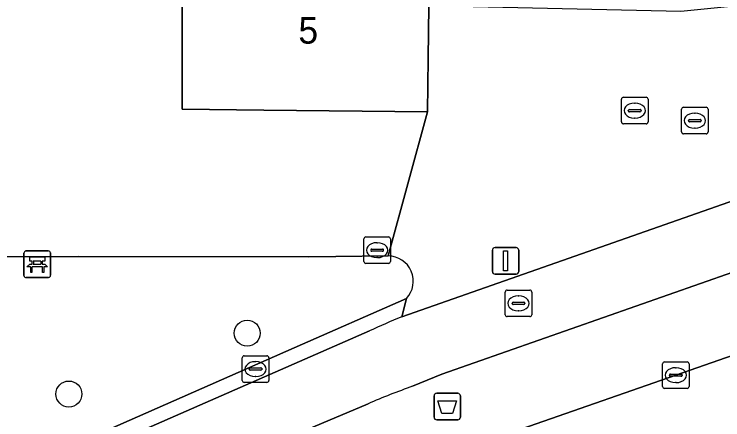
# Model space of a CAD drawing. Extents: x 161087 to 161926, y 382572 to 383873.
# Drawn here: x 161727.08 to 161753.78, y 382829.54 to 382844.81 of the extents above; entities that cross this region are included whole.
import ezdxf

# ---------------------------------------------------------------- set-up
doc = ezdxf.new("R2010")
doc.units = 0
for name, color, linetype in [('IMGEO_Afvalbak', 7, 'Continuous'), ('IMGEO_Bank', 7, 'Continuous'), ('IMGEO_Boom', 7, 'Continuous'), ('IMGEO_Fietspad_gesloten', 7, 'Continuous'), ('IMGEO_Groenvoorziening', 7, 'Continuous'), ('IMGEO_Kolk', 7, 'Continuous'), ('IMGEO_Lichtmast', 7, 'Continuous'), ('IMGEO_Pand', 7, 'Continuous'), ('IMGEO_Pand_nummerreeks', 7, 'Continuous'), ('IMGEO_Rijbaan_lokaal_gesloten', 7, 'Continuous'), ('IMGEO_Rioolput', 7, 'Continuous'), ('IMGEO_Voetpad_open', 7, 'Continuous')]:
    doc.layers.add(name, color=color, linetype=linetype)

msp = doc.modelspace()

# ---------------------------------------------------------------- linework, layer by layer
at = {"layer": 'IMGEO_Afvalbak'}
for p, q in [((161742.903, 382829.642), (161742.903, 382830.442)), ((161742.903, 382830.442), (161742.903, 382829.642)), ((161743.003, 382830.542), (161743.793, 382830.542)), ((161743.793, 382830.542), (161743.003, 382830.542)), ((161743.893, 382830.442), (161743.893, 382829.642)), ((161743.893, 382829.642), (161743.893, 382830.442)), ((161743.793, 382829.542), (161743.003, 382829.542)), ((161743.003, 382829.542), (161743.793, 382829.542))]:
    msp.add_line(p, q, dxfattribs=at)
msp.add_lwpolyline([(161743.046, 382830.256), (161743.75, 382830.256), (161743.601, 382829.786), (161743.195, 382829.786), (161743.046, 382830.256)], dxfattribs=at)
for centre, start, end in [((161743.003, 382830.442), 90, 180), ((161743.003, 382830.442), 90, 180), ((161743.793, 382830.442), 0, 90), ((161743.793, 382830.442), 360, 90), ((161743.003, 382829.642), 180, 270), ((161743.003, 382829.642), 180, 270), ((161743.793, 382829.642), 270, 0), ((161743.793, 382829.642), 270, 0)]:
    msp.add_arc(centre, 0.1, start, end, dxfattribs=at)
at = {"layer": 'IMGEO_Bank'}
for p, q in [((161727.449, 382834.974), (161727.449, 382835.815)), ((161727.449, 382835.815), (161727.449, 382834.974)), ((161727.524, 382835.899), (161728.365, 382835.899)), ((161728.365, 382835.899), (161727.524, 382835.899)), ((161728.449, 382835.824), (161728.449, 382834.983)), ((161728.449, 382834.983), (161728.449, 382835.824)), ((161727.758, 382835.405), (161727.758, 382835.511)), ((161727.802, 382835.511), (161727.802, 382835.405)), ((161728.09, 382835.517), (161727.808, 382835.517)), ((161728.096, 382835.405), (161728.096, 382835.511)), ((161728.14, 382835.511), (161728.14, 382835.405)), ((161728.146, 382835.297), (161727.753, 382835.297)), ((161727.808, 382835.399), (161728.09, 382835.399)), ((161728.374, 382834.899), (161727.533, 382834.899)), ((161727.533, 382834.899), (161728.374, 382834.899))]:
    msp.add_line(p, q, dxfattribs=at)
for points in [[(161727.752, 382835.517), (161727.666, 382835.517), (161727.666, 382835.678), (161728.229, 382835.678), (161728.229, 382835.517), (161728.146, 382835.517)], [(161727.696, 382835.297), (161727.554, 382835.297), (161727.666, 382835.399), (161727.752, 382835.399)], [(161727.746, 382835.29), (161727.746, 382835.083), (161727.703, 382835.083), (161727.703, 382835.29)], [(161728.146, 382835.399), (161728.229, 382835.399), (161728.341, 382835.297), (161728.202, 382835.297)], [(161728.196, 382835.29), (161728.196, 382835.083), (161728.152, 382835.083), (161728.152, 382835.29)]]:
    msp.add_lwpolyline(points, dxfattribs=at)
for centre, radius, start, end in [((161727.527, 382835.821), 0.0779, 92.4484, 184.2845), ((161727.527, 382835.821), 0.0779, 92.4484, 184.2845), ((161728.371, 382835.821), 0.0779, 2.4484, 94.2845), ((161728.371, 382835.821), 0.0779, 2.4484, 94.2845), ((161727.751, 382835.51), 0.00671, 2.8957, 87.1043), ((161727.808, 382835.51), 0.00671, 92.8957, 177.1043), ((161728.09, 382835.51), 0.00671, 2.8957, 87.1043), ((161728.147, 382835.51), 0.00671, 92.8957, 177.1043), ((161727.696, 382835.29), 0.00671, 2.8957, 87.1043), ((161727.753, 382835.29), 0.00671, 92.8957, 177.1043), ((161727.751, 382835.406), 0.00671, 272.8957, 357.1043), ((161727.808, 382835.406), 0.00671, 182.8957, 267.1043), ((161728.09, 382835.406), 0.00671, 272.8957, 357.1043), ((161728.147, 382835.406), 0.00671, 182.8957, 267.1043), ((161728.145, 382835.29), 0.00671, 2.8957, 87.1043), ((161728.202, 382835.29), 0.00671, 92.8957, 177.1043), ((161727.527, 382834.977), 0.0779, 182.4484, 274.2845), ((161727.527, 382834.977), 0.0779, 182.4484, 274.2845), ((161728.371, 382834.977), 0.0779, 272.4484, 4.2845), ((161728.371, 382834.977), 0.0779, 272.4484, 4.2845)]:
    msp.add_arc(centre, radius, start, end, dxfattribs=at)
at = {"layer": 'IMGEO_Boom'}
for centre in [(161735.859, 382832.805), (161729.142, 382830.513)]:
    msp.add_circle(centre, 0.489, dxfattribs=at)
at = {"layer": 'IMGEO_Fietspad_gesloten'}
for points in [[(161770.191, 382843.404), (161741.681, 382833.418)], [(161742.093, 382830.806), (161743.191, 382831.256), (161763.899, 382838.518), (161770.624, 382840.877)], [(161740.467, 382832.888), (161719.327, 382823.646), (161720.925, 382819.562), (161728.389, 382822.563), (161727.398, 382824.655), (161740.413, 382830.148)]]:
    msp.add_lwpolyline(points, dxfattribs=at)
for centre, radius, start, end in [((161752.523, 382806.929), 28.622, 112.2588, 114.9108), ((161751.235, 382804.991), 27.385, 109.5008, 113.2764)]:
    msp.add_arc(centre, radius, start, end, dxfattribs=at)
at = {"layer": 'IMGEO_Groenvoorziening'}
for points in [[(161741.172, 382835.713), (161739.196, 382835.695), (161738.184, 382835.679), (161729.521, 382835.693), (161717.159, 382835.65)], [(161719.905, 382824.464), (161737.635, 382832.249), (161741.859, 382834.108)]]:
    msp.add_lwpolyline(points, dxfattribs=at)
msp.add_arc((161741.164, 382834.76), 0.953, 316.8324, 89.513, dxfattribs=at)
at = {"layer": 'IMGEO_Kolk'}
for p, q in [((161749.961, 382840.757), (161749.961, 382841.609)), ((161750.036, 382841.683), (161750.888, 382841.683)), ((161750.962, 382841.609), (161750.962, 382840.757)), ((161750.449, 382841.463), (161750.474, 382841.463)), ((161750.22, 382841.177), (161750.22, 382841.189)), ((161750.658, 382841.14), (161750.26, 382841.14)), ((161750.263, 382841.226), (161750.661, 382841.226)), ((161750.704, 382841.189), (161750.704, 382841.177)), ((161750.472, 382840.903), (161750.447, 382840.903)), ((161750.888, 382840.683), (161750.036, 382840.683)), ((161740.254, 382835.503), (161740.254, 382836.355)), ((161740.329, 382836.429), (161741.181, 382836.429)), ((161741.255, 382836.355), (161741.255, 382835.503)), ((161740.742, 382836.209), (161740.767, 382836.209)), ((161740.513, 382835.923), (161740.513, 382835.935)), ((161740.951, 382835.886), (161740.553, 382835.886)), ((161740.556, 382835.972), (161740.954, 382835.972)), ((161740.997, 382835.935), (161740.997, 382835.923)), ((161740.765, 382835.649), (161740.74, 382835.649)), ((161741.181, 382835.429), (161740.329, 382835.429)), ((161745.656, 382834.427), (161746.508, 382834.427)), ((161745.581, 382833.501), (161745.581, 382834.353)), ((161746.069, 382834.207), (161746.094, 382834.207)), ((161746.582, 382834.353), (161746.582, 382833.501)), ((161745.84, 382833.921), (161745.84, 382833.933)), ((161746.278, 382833.884), (161745.88, 382833.884)), ((161745.883, 382833.97), (161746.281, 382833.97)), ((161746.324, 382833.933), (161746.324, 382833.921)), ((161746.092, 382833.647), (161746.067, 382833.647)), ((161746.508, 382833.427), (161745.656, 382833.427)), ((161735.675, 382831.026), (161735.675, 382831.878)), ((161735.75, 382831.952), (161736.602, 382831.952)), ((161736.163, 382831.732), (161736.188, 382831.732)), ((161736.676, 382831.878), (161736.676, 382831.026)), ((161751.584, 382831.723), (161752.436, 382831.723)), ((161735.934, 382831.446), (161735.934, 382831.458)), ((161735.977, 382831.495), (161736.375, 382831.495)), ((161736.418, 382831.458), (161736.418, 382831.446)), ((161751.509, 382830.797), (161751.509, 382831.649)), ((161751.997, 382831.503), (161752.022, 382831.503)), ((161752.51, 382831.649), (161752.51, 382830.797)), ((161736.372, 382831.409), (161735.974, 382831.409)), ((161751.768, 382831.217), (161751.768, 382831.229)), ((161751.811, 382831.266), (161752.209, 382831.266)), ((161752.252, 382831.229), (161752.252, 382831.217)), ((161736.602, 382830.952), (161735.75, 382830.952)), ((161736.186, 382831.172), (161736.161, 382831.172)), ((161752.206, 382831.18), (161751.808, 382831.18)), ((161752.02, 382830.943), (161751.995, 382830.943)), ((161752.436, 382830.723), (161751.584, 382830.723))]:
    msp.add_line(p, q, dxfattribs=at)
for points in [[(161749.961, 382840.757), (161749.961, 382841.609)], [(161750.036, 382841.683), (161750.888, 382841.683)], [(161750.962, 382841.609), (161750.962, 382840.757)], [(161750.888, 382840.683), (161750.036, 382840.683)], [(161740.254, 382835.503), (161740.254, 382836.355)], [(161740.329, 382836.429), (161741.181, 382836.429)], [(161741.255, 382836.355), (161741.255, 382835.503)], [(161741.181, 382835.429), (161740.329, 382835.429)], [(161745.656, 382834.427), (161746.508, 382834.427)], [(161745.581, 382833.501), (161745.581, 382834.353)], [(161746.582, 382834.353), (161746.582, 382833.501)], [(161746.508, 382833.427), (161745.656, 382833.427)], [(161735.675, 382831.026), (161735.675, 382831.878)], [(161735.75, 382831.952), (161736.602, 382831.952)], [(161736.676, 382831.878), (161736.676, 382831.026)], [(161751.584, 382831.723), (161752.436, 382831.723)], [(161751.509, 382830.797), (161751.509, 382831.649)], [(161752.51, 382831.649), (161752.51, 382830.797)], [(161736.602, 382830.952), (161735.75, 382830.952)], [(161752.436, 382830.723), (161751.584, 382830.723)]]:
    msp.add_lwpolyline(points, dxfattribs=at)
for centre, radius, start, end in [((161750.038, 382841.607), 0.0765, 91.552, 178.448), ((161750.038, 382841.607), 0.0765, 91.552, 178.448), ((161750.886, 382841.607), 0.0765, 1.552, 88.448), ((161750.886, 382841.607), 0.0765, 1.552, 88.448), ((161750.26, 382841.186), 0.0403, 85.8775, 175.7526), ((161750.257, 382841.176), 0.0366, 178.938, 274.7102), ((161750.661, 382841.183), 0.043, 264.8664, 352.4533), ((161750.665, 382841.188), 0.0386, 1.7309, 96.639), ((161750.038, 382840.759), 0.0765, 181.552, 268.448), ((161750.038, 382840.759), 0.0765, 181.552, 268.448), ((161750.886, 382840.759), 0.0765, 271.552, 358.448), ((161750.886, 382840.759), 0.0765, 271.552, 358.448), ((161740.331, 382836.353), 0.0765, 91.552, 178.448), ((161740.331, 382836.353), 0.0765, 91.552, 178.448), ((161741.179, 382836.353), 0.0765, 1.552, 88.448), ((161741.179, 382836.353), 0.0765, 1.552, 88.448), ((161740.553, 382835.932), 0.0403, 85.8775, 175.7526), ((161740.55, 382835.922), 0.0366, 178.938, 274.7102), ((161740.954, 382835.929), 0.043, 264.8664, 352.4533), ((161740.958, 382835.934), 0.0386, 1.7309, 96.639), ((161740.331, 382835.505), 0.0765, 181.552, 268.448), ((161740.331, 382835.505), 0.0765, 181.552, 268.448), ((161741.179, 382835.505), 0.0765, 271.552, 358.448), ((161741.179, 382835.505), 0.0765, 271.552, 358.448), ((161745.658, 382834.351), 0.0765, 91.552, 178.448), ((161745.658, 382834.351), 0.0765, 91.552, 178.448), ((161746.506, 382834.351), 0.0765, 1.552, 88.448), ((161746.506, 382834.351), 0.0765, 1.552, 88.448), ((161745.88, 382833.93), 0.0403, 85.8775, 175.7526), ((161745.877, 382833.92), 0.0366, 178.938, 274.7102), ((161746.281, 382833.927), 0.043, 264.8664, 352.4533), ((161746.285, 382833.932), 0.0386, 1.7309, 96.639), ((161745.658, 382833.503), 0.0765, 181.552, 268.448), ((161745.658, 382833.503), 0.0765, 181.552, 268.448), ((161746.506, 382833.503), 0.0765, 271.552, 358.448), ((161746.506, 382833.503), 0.0765, 271.552, 358.448), ((161735.752, 382831.876), 0.0765, 91.552, 178.448), ((161735.752, 382831.876), 0.0765, 91.552, 178.448), ((161736.6, 382831.876), 0.0765, 1.552, 88.448), ((161736.6, 382831.876), 0.0765, 1.552, 88.448), ((161751.586, 382831.647), 0.0765, 91.552, 178.448), ((161751.586, 382831.647), 0.0765, 91.552, 178.448), ((161752.434, 382831.647), 0.0765, 1.552, 88.448), ((161752.434, 382831.647), 0.0765, 1.552, 88.448), ((161735.974, 382831.455), 0.0403, 85.8775, 175.7526), ((161736.379, 382831.457), 0.0386, 1.7309, 96.639), ((161735.971, 382831.445), 0.0366, 178.938, 274.7102), ((161736.375, 382831.452), 0.043, 264.8664, 352.4533), ((161751.808, 382831.226), 0.0403, 85.8775, 175.7526), ((161751.805, 382831.216), 0.0366, 178.938, 274.7102), ((161752.209, 382831.223), 0.043, 264.8664, 352.4533), ((161752.213, 382831.228), 0.0386, 1.7309, 96.639), ((161735.752, 382831.028), 0.0765, 181.552, 268.448), ((161735.752, 382831.028), 0.0765, 181.552, 268.448), ((161736.6, 382831.028), 0.0765, 271.552, 358.448), ((161736.6, 382831.028), 0.0765, 271.552, 358.448), ((161751.586, 382830.799), 0.0765, 181.552, 268.448), ((161751.586, 382830.799), 0.0765, 181.552, 268.448), ((161752.434, 382830.799), 0.0765, 271.552, 358.448), ((161752.434, 382830.799), 0.0765, 271.552, 358.448)]:
    msp.add_arc(centre, radius, start, end, dxfattribs=at)
for centre, major_axis, ratio, start_param, end_param in [((161750.448, 382841.183), (-0.387, 0.002), 0.722429, 4.712389, 7.853982), ((161750.473, 382841.183), (-0.39, 0.002), 0.717154, 1.570796, 4.712389), ((161740.741, 382835.929), (-0.387, 0.002), 0.722429, 4.712389, 7.853982), ((161740.766, 382835.929), (-0.39, 0.002), 0.717154, 1.570796, 4.712389), ((161746.068, 382833.927), (-0.387, 0.002), 0.722429, 4.712389, 7.853982), ((161746.093, 382833.927), (-0.39, 0.002), 0.717154, 1.570796, 4.712389), ((161736.162, 382831.452), (-0.387, 0.002), 0.722429, 4.712389, 7.853982), ((161736.187, 382831.452), (-0.39, 0.002), 0.717154, 1.570796, 4.712389), ((161751.996, 382831.223), (-0.387, 0.002), 0.722429, 4.712389, 7.853982), ((161752.021, 382831.223), (-0.39, 0.002), 0.717154, 1.570796, 4.712389)]:
    msp.add_ellipse(centre, major_axis=major_axis, ratio=ratio, start_param=start_param, end_param=end_param, dxfattribs=at)
at = {"layer": 'IMGEO_Lichtmast'}
for p, q in [((161745.199, 382836.025), (161745.989, 382836.025)), ((161745.989, 382836.025), (161745.199, 382836.025)), ((161745.099, 382835.125), (161745.099, 382835.925)), ((161745.099, 382835.925), (161745.099, 382835.125)), ((161746.089, 382835.925), (161746.089, 382835.125)), ((161746.089, 382835.125), (161746.089, 382835.925)), ((161745.989, 382835.025), (161745.199, 382835.025)), ((161745.199, 382835.025), (161745.989, 382835.025))]:
    msp.add_line(p, q, dxfattribs=at)
msp.add_lwpolyline([(161745.519, 382835.9), (161745.669, 382835.9), (161745.669, 382835.15), (161745.519, 382835.15), (161745.519, 382835.9)], dxfattribs=at)
for centre, start, end in [((161745.199, 382835.925), 90, 180), ((161745.199, 382835.925), 90, 180), ((161745.989, 382835.925), 0, 90), ((161745.989, 382835.925), 360, 90), ((161745.199, 382835.125), 180, 270), ((161745.199, 382835.125), 180, 270), ((161745.989, 382835.125), 270, 0), ((161745.989, 382835.125), 270, 0)]:
    msp.add_arc(centre, 0.1, start, end, dxfattribs=at)
at = {"layer": 'IMGEO_Pand'}
msp.add_lwpolyline([(161742.633, 382851.876), (161734.628, 382851.868), (161734.627, 382853.398), (161737.256, 382853.848), (161737.041, 382856.737), (161732.846, 382855.907), (161732.85, 382850.115), (161732.855, 382845.176), (161733.414, 382845.17), (161733.41, 382841.235), (161736.492, 382841.202), (161742.655, 382841.135), (161742.678, 382843.14), (161742.7, 382845.123)], close=True, dxfattribs=at)
at = {"layer": 'IMGEO_Rijbaan_lokaal_gesloten'}
msp.add_lwpolyline([(161786.082, 382843.125), (161783.978, 382842.401), (161777.336, 382840.072), (161764.885, 382835.707), (161764.683, 382835.636), (161752.01, 382831.223), (161741.488, 382827.556), (161736.346, 382825.698), (161735.002, 382825.222), (161737.362, 382819.209), (161767.109, 382829.547), (161774.717, 382832.23), (161779.972, 382833.544), (161784.515, 382834.256), (161788.346, 382834.584), (161795.133, 382834.857), (161826.222, 382836.445), (161841.766, 382837.156)], dxfattribs=at)
at = {"layer": 'IMGEO_Rioolput'}
for p, q in [((161752.225, 382840.381), (161752.225, 382841.233)), ((161752.3, 382841.307), (161753.152, 382841.307)), ((161752.713, 382841.087), (161752.738, 382841.087)), ((161753.226, 382841.233), (161753.226, 382840.381)), ((161752.484, 382840.801), (161752.484, 382840.813)), ((161752.527, 382840.85), (161752.925, 382840.85)), ((161752.968, 382840.813), (161752.968, 382840.801)), ((161752.922, 382840.764), (161752.524, 382840.764)), ((161753.152, 382840.307), (161752.3, 382840.307)), ((161752.736, 382840.527), (161752.711, 382840.527))]:
    msp.add_line(p, q, dxfattribs=at)
for points in [[(161752.225, 382840.381), (161752.225, 382841.233)], [(161752.3, 382841.307), (161753.152, 382841.307)], [(161753.226, 382841.233), (161753.226, 382840.381)], [(161753.152, 382840.307), (161752.3, 382840.307)]]:
    msp.add_lwpolyline(points, dxfattribs=at)
for centre, radius, start, end in [((161752.302, 382841.231), 0.0765, 91.552, 178.448), ((161752.302, 382841.231), 0.0765, 91.552, 178.448), ((161753.15, 382841.231), 0.0765, 1.552, 88.448), ((161753.15, 382841.231), 0.0765, 1.552, 88.448), ((161752.524, 382840.81), 0.0403, 85.8775, 175.7526), ((161752.521, 382840.8), 0.0366, 178.938, 274.7102), ((161752.925, 382840.807), 0.043, 264.8664, 352.4533), ((161752.929, 382840.812), 0.0386, 1.7309, 96.639), ((161752.302, 382840.383), 0.0765, 181.552, 268.448), ((161752.302, 382840.383), 0.0765, 181.552, 268.448), ((161753.15, 382840.383), 0.0765, 271.552, 358.448), ((161753.15, 382840.383), 0.0765, 271.552, 358.448)]:
    msp.add_arc(centre, radius, start, end, dxfattribs=at)
for centre, major_axis, ratio, start_param, end_param in [((161752.712, 382840.807), (-0.387, 0.002), 0.722429, 4.712389, 7.853982), ((161752.737, 382840.807), (-0.39, 0.002), 0.717154, 1.570796, 4.712389)]:
    msp.add_ellipse(centre, major_axis=major_axis, ratio=ratio, start_param=start_param, end_param=end_param, dxfattribs=at)
at = {"layer": 'IMGEO_Voetpad_open'}
for points in [[(161777.714, 382844.949), (161784.962, 382845.502), (161786.758, 382845.61), (161787.54, 382845.621), (161787.516, 382846.12), (161787.523, 382848.445), (161784.52, 382848.144), (161784.334, 382850.091), (161755.019, 382847.28), (161755.217, 382845.219), (161752.2, 382844.92), (161742.7, 382845.123), (161742.678, 382843.14), (161742.655, 382841.135), (161741.172, 382835.713)], [(161741.859, 382834.108), (161741.681, 382833.418), (161770.191, 382843.404)], [(161764.683, 382835.636), (161764.885, 382835.707), (161763.899, 382838.518), (161743.191, 382831.256), (161742.093, 382830.806)], [(161740.413, 382830.148), (161727.398, 382824.655), (161728.389, 382822.563), (161735.002, 382825.222), (161736.346, 382825.698), (161741.488, 382827.556), (161752.01, 382831.223), (161764.683, 382835.636)], [(161741.681, 382833.418), (161741.859, 382834.108), (161737.635, 382832.249), (161719.905, 382824.464)], [(161718.955, 382824.54), (161719.327, 382823.646), (161740.467, 382832.888)]]:
    msp.add_lwpolyline(points, dxfattribs=at)
msp.add_lwpolyline([(161742.655, 382841.135), (161736.492, 382841.202), (161733.41, 382841.235), (161733.414, 382845.17), (161732.855, 382845.176), (161731.894, 382845.147), (161716.718, 382845.131), (161715.114, 382846.906), (161714.877, 382846.863), (161717.159, 382835.65), (161729.521, 382835.693), (161738.184, 382835.679), (161739.196, 382835.695), (161741.172, 382835.713)], close=True, dxfattribs=at)
for centre, radius, start, end in [((161741.164, 382834.76), 0.953, 316.8324, 89.513), ((161752.523, 382806.929), 28.622, 112.2588, 114.9108), ((161751.235, 382804.991), 27.385, 109.5008, 113.2764)]:
    msp.add_arc(centre, radius, start, end, dxfattribs=at)

# ---------------------------------------------------------------- texts
at = {"layer": 'IMGEO_Pand_nummerreeks'}
msp.add_text('5', height=1, rotation=359.3803, dxfattribs=at).set_placement((161737.785, 382843.708))

doc.saveas('drawing.dxf')
